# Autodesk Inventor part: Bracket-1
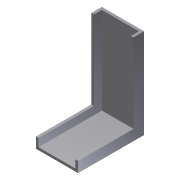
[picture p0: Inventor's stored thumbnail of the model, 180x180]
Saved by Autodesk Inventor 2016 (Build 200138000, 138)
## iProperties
Shininess: 77.0
Length Units: 11269
Angle Units: 11279
Time Units: 11290
Mass Units: 11283
Length Display Precision: 3
Angle Display Precision: 2
Created: 2002-04
Part Number: Bracket-1
Document SubType Name: Modeling
Density: 1 g/cm^3
Material: Generic
Appearance: Default
Density: 0.0
Volumn: 0.0
Area: 0.0
PropertySet Name: Model Information
Control State: 0
Master: False
Checked Out: False
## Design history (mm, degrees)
node "Sketch1"
sketch "Sketch2"
  geometry: L1 (-4.258, 23.699)-(-4.258, -18.801); L2 (-4.258, -18.801)-(26.992, -18.801); L3 (26.992, -18.801)-(26.992, -13.801); L4 (26.992, -13.801)-(0.742, -13.801); L5 (0.742, -13.801)-(0.742, 23.699); L6 (0.742, 23.699)-(-4.258, 23.699)
  constraints: 12 end point, 4 parallel, 2 perpendicular, 1 vertical
  dimensions: "d0" = 31.25 distance of L1.end L2.end; "d1" = 42.5 distance of L1.start L1.end; "d2" = 5 distance of L2.end L3.end
extrude "Extrusion1" new body sketch "Sketch2" stored distance "d3" = 20; taper "d4" = 0 deg
shell "Shell1" dims "d5" = 1.25
body "Solid1"
